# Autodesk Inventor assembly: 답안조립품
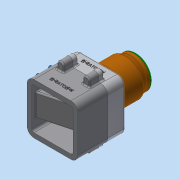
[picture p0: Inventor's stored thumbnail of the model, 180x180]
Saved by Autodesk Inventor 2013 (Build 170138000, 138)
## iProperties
Created: 2018-01
Part Number: 답안조립품
Document SubType Name: Assembly
Designer: dgall
Author: dgall
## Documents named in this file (9)
- C:\Users\dgall\Desktop\480107v1013\답안조립품.iam
- C:\Users\dgall\Desktop\480107v1013\1.본체.ipt
- C:\Users\dgall\Desktop\480107v1013\본체커버.ipt
- C:\Users\dgall\Desktop\480107v1013\볼트 M3x12.ipt
- C:\Users\dgall\Desktop\480107v1013\볼트 M4x12.ipt
- C:\Users\dgall\Desktop\480107v1013\용기.ipt
- C:\Users\dgall\Desktop\480107v1013\용기캡.ipt
- C:\Users\dgall\Desktop\480107v1013\핸들.ipt
- C:\Users\dgall\Desktop\480107v1013\핸들축.ipt
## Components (3 placed, 3 different names)
1. 1.본체:1
2. 핸들:1
3. 핸들축:1
